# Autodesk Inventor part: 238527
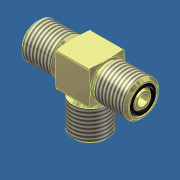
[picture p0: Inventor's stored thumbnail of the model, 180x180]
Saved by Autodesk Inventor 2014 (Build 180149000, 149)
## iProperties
Shininess: 20.0
Length Units: 11272
Angle Units: 11279
Time Units: 11290
Mass Units: 11286
Length Display Precision: 3
Angle Display Precision: 2
Company: Autodesk, Inc.
Created: 2002-06
Part Number: 238527
Material: Stainless Steel, 440C
Description: Fitting; TE-A9C9C912-(SS)
Document SubType Name: Modeling
Designer: Autodesk, Inc.
Density: 7.75 g/cm^3
Mass: 524.175 g
Surface Area: 254.141 cm^2
Volume: 67.6355 cm^3
Appearance: Stainless Steel
Density: 0.0
Volumn: 0.0
Area: 0.0
PropertySet Name: Model Information
Control State: 0
Master: False
Checked Out: False
Last Check In By: JT
Last Check In Date: 2003-06-20
Title: Fitting; TE-A9C9C912-(SS)
Author: Autodesk, Inc.
Comments: -
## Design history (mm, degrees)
derived "C9C9C9_C9C9A9_C9A9C9.ipt"
body "Solid1"
tag "TaggingFeature2"
feature "Solid1::C9C9C9_C9C9A9_C9A9C9.ipt" dims "ScaleForDerivedMember" = 10
